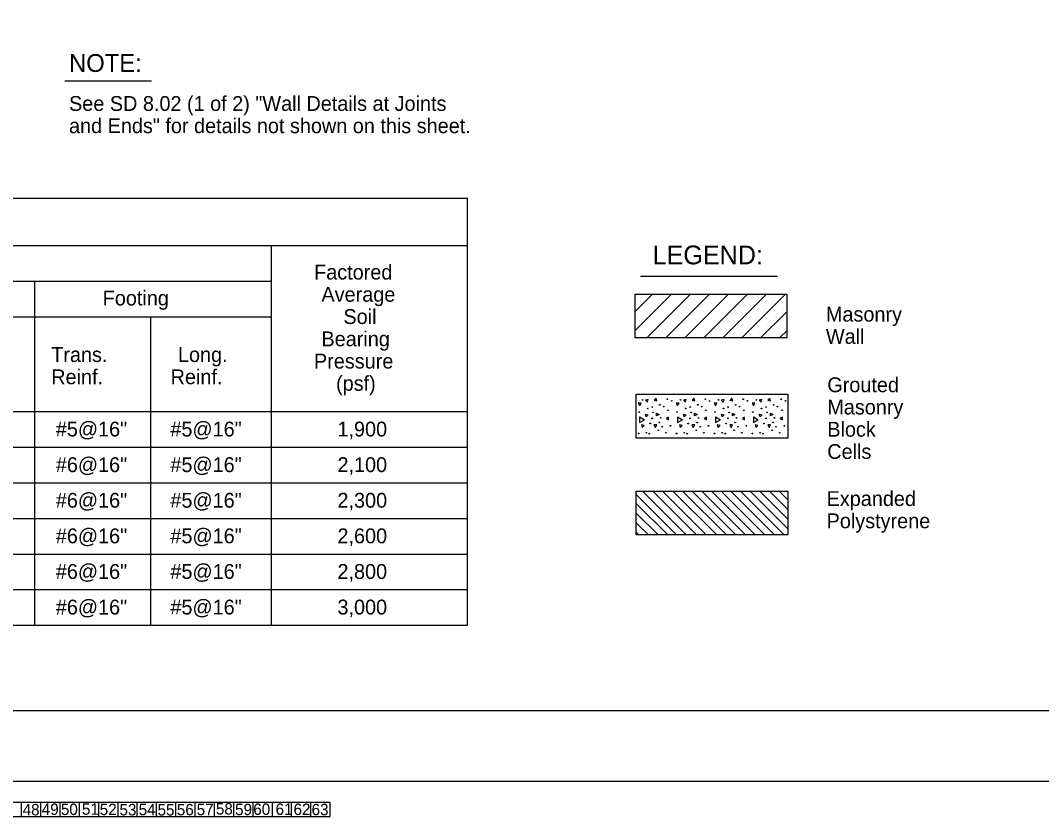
# Model space of a CAD drawing. Extents: x 0 to 2.83, y -0.03 to 1.83.
# Drawn here: x 0.9 to 1.796, y -0.031 to 0.668 of the extents above; entities that cross this region are included whole.
import ezdxf

# ---------------------------------------------------------------- set-up
doc = ezdxf.new("R2010")
doc.units = 0
for name, color, linetype in [('48', 7, 'Continuous'), ('49', 7, 'Continuous'), ('50', 7, 'Continuous'), ('51', 7, 'Continuous'), ('52', 7, 'Continuous'), ('53', 7, 'Continuous'), ('54', 7, 'Continuous'), ('55', 7, 'Continuous'), ('56', 7, 'Continuous'), ('57', 7, 'Continuous'), ('58', 7, 'Continuous'), ('59', 7, 'Continuous'), ('60', 7, 'Continuous'), ('61', 7, 'Continuous'), ('62', 7, 'Continuous'), ('63', 7, 'Continuous')]:
    doc.layers.add(name, color=color, linetype=linetype)

msp = doc.modelspace()

# ---------------------------------------------------------------- linework, layer by layer
at = {"layer": '50'}
for p, q in [((1.45497, 0.42794), (1.43957, 0.41254)), ((1.47163, 0.42794), (1.43957, 0.39587)), ((1.48829, 0.42794), (1.44992, 0.38956)), ((1.5049, 0.42794), (1.46651, 0.38956)), ((1.52157, 0.42794), (1.48318, 0.38956)), ((1.53823, 0.42794), (1.49985, 0.38956)), ((1.5549, 0.42794), (1.51652, 0.38956)), ((1.57157, 0.42794), (1.53319, 0.38956)), ((1.5727, 0.41241), (1.54985, 0.38956)), ((1.5727, 0.39575), (1.56651, 0.38956)), ((1.44051, 0.25203), (1.4761, 0.21644)), ((1.44618, 0.25482), (1.48457, 0.21644)), ((1.45525, 0.25482), (1.49364, 0.21644)), ((1.46372, 0.25482), (1.5021, 0.21644)), ((1.47289, 0.25482), (1.51127, 0.21644)), ((1.48135, 0.25482), (1.51973, 0.21644)), ((1.48982, 0.25482), (1.5282, 0.21644)), ((1.49828, 0.25482), (1.53666, 0.21644)), ((1.50674, 0.25482), (1.54512, 0.21644)), ((1.51521, 0.25482), (1.55359, 0.21644)), ((1.52367, 0.25482), (1.56205, 0.21644)), ((1.53213, 0.25482), (1.57051, 0.21644)), ((1.5406, 0.25482), (1.57365, 0.22177)), ((1.54906, 0.25482), (1.57365, 0.23023)), ((1.55752, 0.25482), (1.57365, 0.23869)), ((1.56599, 0.25482), (1.57365, 0.24716)), ((1.44052, 0.24417), (1.46825, 0.21644)), ((1.44052, 0.2357), (1.45978, 0.21644)), ((1.44052, 0.22724), (1.45132, 0.21644)), ((1.44052, 0.21878), (1.44286, 0.21644))]:
    msp.add_line(p, q, dxfattribs=at)
for centre in [(1.44625, 0.33498), (1.46796, 0.33564), (1.47179, 0.33415), (1.47953, 0.33498), (1.50124, 0.33564), (1.50508, 0.33415), (1.51282, 0.33498), (1.53453, 0.33564), (1.53836, 0.33415), (1.5461, 0.33498), (1.56781, 0.33564), (1.57164, 0.33415), (1.44317, 0.32437), (1.4507, 0.32745), (1.45471, 0.32877), (1.45563, 0.32406), (1.46136, 0.33075), (1.46479, 0.32917), (1.46853, 0.32591), (1.47645, 0.32437), (1.48398, 0.32745), (1.48799, 0.32877), (1.48892, 0.32406), (1.49464, 0.33075), (1.49808, 0.32917), (1.50182, 0.32591), (1.50973, 0.32437), (1.51727, 0.32745), (1.52128, 0.32877), (1.5222, 0.32406), (1.52793, 0.33075), (1.53136, 0.32917), (1.5351, 0.32591), (1.54302, 0.32437), (1.55055, 0.32745), (1.55456, 0.32877), (1.55548, 0.32406), (1.56121, 0.33075), (1.56464, 0.32917), (1.56838, 0.32591), (1.4529, 0.31433), (1.45462, 0.31886), (1.46088, 0.31516), (1.46211, 0.31917), (1.48618, 0.31433), (1.4879, 0.31886), (1.49416, 0.31516), (1.49539, 0.31917), (1.51947, 0.31433), (1.52118, 0.31886), (1.52744, 0.31516), (1.52868, 0.31917), (1.55275, 0.31433), (1.55447, 0.31886), (1.56073, 0.31516), (1.56196, 0.31917), (1.44273, 0.30552), (1.44956, 0.30622), (1.45211, 0.30539), (1.46008, 0.30834), (1.46343, 0.31151), (1.46673, 0.30622), (1.47078, 0.31221), (1.47601, 0.30552), (1.48284, 0.30622), (1.48539, 0.30539), (1.49336, 0.30834), (1.49671, 0.31151), (1.50001, 0.30622), (1.50407, 0.31221), (1.50929, 0.30552), (1.51613, 0.30622), (1.51868, 0.30539), (1.52664, 0.30834), (1.52999, 0.31151), (1.53329, 0.30622), (1.53735, 0.31221), (1.54258, 0.30552), (1.54941, 0.30622), (1.55196, 0.30539), (1.55993, 0.30834), (1.56328, 0.31151), (1.56658, 0.30622), (1.57063, 0.31221)]:
    msp.add_circle(centre, 0.000305, dxfattribs=at)
at = {"layer": '51'}
for p, q in [((1.4436, 0.32009), (1.4436, 0.31513)), ((1.4436, 0.32008), (1.4479, 0.31762)), ((1.4436, 0.31513), (1.4479, 0.3176)), ((1.47688, 0.32009), (1.47688, 0.31513)), ((1.47688, 0.32008), (1.48118, 0.31762)), ((1.47688, 0.31513), (1.48118, 0.3176)), ((1.51017, 0.32009), (1.51017, 0.31513)), ((1.51017, 0.32008), (1.51447, 0.31762)), ((1.51017, 0.31513), (1.51447, 0.3176)), ((1.54345, 0.32009), (1.54345, 0.31513)), ((1.54345, 0.32008), (1.54775, 0.31762)), ((1.54345, 0.31513), (1.54775, 0.3176))]:
    msp.add_line(p, q, dxfattribs=at)
at = {"layer": '52'}
for p, q in [((1.44492, 0.33228), (1.44245, 0.33226)), ((1.44245, 0.33227), (1.44368, 0.33012)), ((1.44368, 0.33012), (1.44493, 0.33227)), ((1.45117, 0.33542), (1.44877, 0.33476)), ((1.44877, 0.33477), (1.45052, 0.33301)), ((1.45052, 0.33301), (1.45117, 0.33541)), ((1.45637, 0.33478), (1.45877, 0.33413)), ((1.4581, 0.33654), (1.45638, 0.33478)), ((1.45877, 0.33413), (1.45812, 0.33653)), ((1.4782, 0.33228), (1.47573, 0.33226)), ((1.47573, 0.33227), (1.47697, 0.33012)), ((1.47697, 0.33012), (1.47822, 0.33227)), ((1.48445, 0.33542), (1.48205, 0.33476)), ((1.48205, 0.33477), (1.4838, 0.33301)), ((1.4838, 0.33301), (1.48445, 0.33541)), ((1.48965, 0.33478), (1.49205, 0.33413)), ((1.49138, 0.33654), (1.48967, 0.33478)), ((1.49205, 0.33413), (1.4914, 0.33653)), ((1.51148, 0.33228), (1.50902, 0.33226)), ((1.50902, 0.33227), (1.51025, 0.33012)), ((1.51025, 0.33012), (1.5115, 0.33227)), ((1.51773, 0.33542), (1.51533, 0.33476)), ((1.51533, 0.33477), (1.51708, 0.33301)), ((1.51708, 0.33301), (1.51773, 0.33541)), ((1.52293, 0.33478), (1.52533, 0.33413)), ((1.52467, 0.33654), (1.52295, 0.33478)), ((1.52533, 0.33413), (1.52468, 0.33653)), ((1.54477, 0.33228), (1.5423, 0.33226)), ((1.5423, 0.33227), (1.54353, 0.33012)), ((1.54353, 0.33012), (1.54478, 0.33227)), ((1.55102, 0.33542), (1.54862, 0.33476)), ((1.54862, 0.33477), (1.55037, 0.33301)), ((1.55037, 0.33301), (1.55102, 0.33541)), ((1.55622, 0.33478), (1.55862, 0.33413)), ((1.55795, 0.33654), (1.55623, 0.33478)), ((1.55862, 0.33413), (1.55797, 0.33653)), ((1.45857, 0.32093), (1.45857, 0.32341)), ((1.45857, 0.3234), (1.46072, 0.32218)), ((1.49185, 0.32093), (1.49185, 0.32341)), ((1.49185, 0.3234), (1.494, 0.32218)), ((1.52513, 0.32093), (1.52513, 0.32341)), ((1.52513, 0.3234), (1.52728, 0.32218)), ((1.55842, 0.32093), (1.55842, 0.32341)), ((1.55842, 0.3234), (1.56057, 0.32218)), ((1.44945, 0.3202), (1.4488, 0.32259)), ((1.44882, 0.32259), (1.4512, 0.32196)), ((1.4512, 0.32195), (1.44945, 0.3202)), ((1.46072, 0.32217), (1.45857, 0.32093)), ((1.46693, 0.31869), (1.46908, 0.31744)), ((1.46907, 0.31993), (1.46695, 0.31868)), ((1.46908, 0.31744), (1.46908, 0.31992)), ((1.48273, 0.3202), (1.48208, 0.32259)), ((1.4821, 0.32259), (1.48448, 0.32196)), ((1.48448, 0.32195), (1.48273, 0.3202)), ((1.494, 0.32217), (1.49185, 0.32093)), ((1.50022, 0.31869), (1.50237, 0.31744)), ((1.50235, 0.31993), (1.50023, 0.31868)), ((1.50237, 0.31744), (1.50237, 0.31992)), ((1.51602, 0.3202), (1.51537, 0.32259)), ((1.51538, 0.32259), (1.51777, 0.32196)), ((1.51777, 0.32195), (1.51602, 0.3202)), ((1.52728, 0.32217), (1.52513, 0.32093)), ((1.5335, 0.31869), (1.53565, 0.31744)), ((1.53563, 0.31993), (1.53352, 0.31868)), ((1.53565, 0.31744), (1.53565, 0.31992)), ((1.5493, 0.3202), (1.54865, 0.32259)), ((1.54867, 0.32259), (1.55105, 0.32196)), ((1.55105, 0.32195), (1.5493, 0.3202)), ((1.56057, 0.32217), (1.55842, 0.32093)), ((1.56678, 0.31869), (1.56893, 0.31744)), ((1.56892, 0.31993), (1.5668, 0.31868)), ((1.56893, 0.31744), (1.56893, 0.31992)), ((1.44523, 0.31311), (1.44588, 0.31071)), ((1.44763, 0.31248), (1.44525, 0.3131)), ((1.44588, 0.31071), (1.44763, 0.31247)), ((1.45865, 0.31309), (1.45617, 0.31307)), ((1.45617, 0.31308), (1.45742, 0.31093)), ((1.45742, 0.31093), (1.45865, 0.31308)), ((1.47852, 0.31311), (1.47917, 0.31071)), ((1.48092, 0.31248), (1.47853, 0.3131)), ((1.47917, 0.31071), (1.48092, 0.31247)), ((1.49193, 0.31309), (1.48945, 0.31307)), ((1.48945, 0.31308), (1.4907, 0.31093)), ((1.4907, 0.31093), (1.49193, 0.31308)), ((1.5118, 0.31311), (1.51245, 0.31071)), ((1.5142, 0.31248), (1.51182, 0.3131)), ((1.51245, 0.31071), (1.5142, 0.31247)), ((1.52522, 0.31309), (1.52273, 0.31307)), ((1.52273, 0.31308), (1.52398, 0.31093)), ((1.52398, 0.31093), (1.52522, 0.31308)), ((1.54508, 0.31311), (1.54573, 0.31071)), ((1.54748, 0.31248), (1.5451, 0.3131)), ((1.54573, 0.31071), (1.54748, 0.31247)), ((1.5585, 0.31309), (1.55602, 0.31307)), ((1.55602, 0.31308), (1.55727, 0.31093)), ((1.55727, 0.31093), (1.5585, 0.31308))]:
    msp.add_line(p, q, dxfattribs=at)
at = {"layer": '55'}
for p, q in [((0.13257, 0.51222), (1.29243, 0.51222)), ((1.29243, 0.13722), (1.29243, 0.51222)), ((0.13257, 0.47055), (1.29243, 0.47055)), ((1.1206, 0.13722), (1.1206, 0.47055)), ((0.62096, 0.4393), (1.1206, 0.4393)), ((0.9128, 0.13722), (0.9128, 0.4393)), ((1.56471, 0.44341), (1.44425, 0.44341)), ((0.62096, 0.40805), (1.1206, 0.40805)), ((1.0146, 0.13722), (1.0146, 0.40805)), ((0.13257, 0.32472), (1.29243, 0.32472)), ((0.13257, 0.29347), (1.29243, 0.29347)), ((0.13257, 0.26222), (1.29243, 0.26222)), ((0.13257, 0.23097), (1.29243, 0.23097)), ((0.13257, 0.19972), (1.29243, 0.19972)), ((0.13257, 0.16847), (1.29243, 0.16847)), ((0.13257, 0.13722), (1.29243, 0.13722))]:
    msp.add_line(p, q, dxfattribs=at)
for points in [[(1.43957, 0.42794), (1.5727, 0.42794), (1.5727, 0.38956), (1.43957, 0.38956)], [(1.44052, 0.33997), (1.57365, 0.33997), (1.57365, 0.30159), (1.44052, 0.30159)], [(1.44052, 0.25482), (1.57365, 0.25482), (1.57365, 0.21644), (1.44052, 0.21644)]]:
    msp.add_lwpolyline(points, close=True, dxfattribs=at)
at = {"layer": '57'}
msp.add_line((0.9391, 0.61521), (1.01507, 0.61521), dxfattribs=at)
at = {"layer": '62'}
for p, q in [((0.10494, -0.01804), (1.17174, -0.01804)), ((0.10496, -0.0181), (1.17175, -0.0181)), ((0.90081, -0.01804), (0.90081, -0.03074)), ((0.90082, -0.0181), (0.90082, -0.0308)), ((0.91774, -0.01804), (0.91774, -0.03074)), ((0.91775, -0.0181), (0.91775, -0.0308)), ((0.93468, -0.01804), (0.93468, -0.03074)), ((0.93469, -0.0181), (0.93469, -0.0308)), ((0.95161, -0.01804), (0.95161, -0.03074)), ((0.95162, -0.0181), (0.95162, -0.0308)), ((0.96854, -0.01804), (0.96854, -0.03074)), ((0.96855, -0.0181), (0.96855, -0.0308)), ((0.98548, -0.01804), (0.98548, -0.03074)), ((0.98549, -0.0181), (0.98549, -0.0308)), ((1.00241, -0.01804), (1.00241, -0.03074)), ((1.00242, -0.0181), (1.00242, -0.0308)), ((1.01934, -0.01804), (1.01934, -0.03074)), ((1.01935, -0.0181), (1.01935, -0.0308)), ((1.03628, -0.01804), (1.03628, -0.03074)), ((1.03629, -0.0181), (1.03629, -0.0308)), ((1.05321, -0.01804), (1.05321, -0.03074)), ((1.05322, -0.0181), (1.05322, -0.0308)), ((1.07014, -0.01804), (1.07014, -0.03074)), ((1.07015, -0.0181), (1.07015, -0.0308)), ((1.08708, -0.01804), (1.08708, -0.03074)), ((1.08709, -0.0181), (1.08709, -0.0308)), ((1.10401, -0.01804), (1.10401, -0.03074)), ((1.10402, -0.0181), (1.10402, -0.0308)), ((1.12094, -0.01804), (1.12094, -0.03074)), ((1.12095, -0.0181), (1.12095, -0.0308)), ((1.13788, -0.01804), (1.13788, -0.03074)), ((1.13789, -0.0181), (1.13789, -0.0308)), ((1.15481, -0.01804), (1.15481, -0.03074)), ((1.15482, -0.0181), (1.15482, -0.0308)), ((1.17174, -0.01804), (1.17174, -0.03074)), ((1.17175, -0.0181), (1.17175, -0.0308)), ((0.10494, -0.03074), (1.17174, -0.03074)), ((0.10496, -0.0308), (1.17175, -0.0308))]:
    msp.add_line(p, q, dxfattribs=at)
at = {"layer": '63'}
msp.add_line((2.83333, 0), (0, 0), dxfattribs=at)
msp.add_lwpolyline([(2.72918, 1.77077), (0.10418, 1.77077), (0.10418, 0.06244), (2.72918, 0.06244)], close=True, dxfattribs=at)

# ---------------------------------------------------------------- texts
at = {"layer": '48'}
for p in [(0.90205, -0.02969), (0.90206, -0.02975)]:
    msp.add_text('48', height=0.01, dxfattribs=at).set_placement(p)
at = {"layer": '49'}
for p in [(0.91882, -0.02929), (0.91883, -0.02935)]:
    msp.add_text('49', height=0.01, dxfattribs=at).set_placement(p)
at = {"layer": '50'}
for p in [(0.93563, -0.02938), (0.93564, -0.02944)]:
    msp.add_text('50', height=0.01, dxfattribs=at).set_placement(p)
at = {"layer": '51'}
for p in [(0.95407, -0.02918), (0.95408, -0.02923)]:
    msp.add_text('51', height=0.01, dxfattribs=at).set_placement(p)
at = {"layer": '52'}
for p in [(0.96972, -0.02946), (0.96973, -0.02952)]:
    msp.add_text('52', height=0.01, dxfattribs=at).set_placement(p)
at = {"layer": '53'}
for p in [(0.98705, -0.0297), (0.98707, -0.02976)]:
    msp.add_text('53', height=0.01, dxfattribs=at).set_placement(p)
at = {"layer": '54'}
for p in [(1.0039, -0.02958), (1.00392, -0.02964)]:
    msp.add_text('54', height=0.01, dxfattribs=at).set_placement(p)
at = {"layer": '55'}
for s, height, p in [('Masonry ', 0.013021, (1.60713, 0.4038)), ('Wall', 0.013021, (1.60713, 0.38427)), ('Grouted ', 0.013021, (1.60833, 0.34181)), ('Masonry ', 0.013021, (1.60833, 0.32228)), ('Block ', 0.013021, (1.60833, 0.30275)), ('Cells', 0.013021, (1.60833, 0.28322)), ('Expanded ', 0.013021, (1.60773, 0.24188)), ('Polystyrene', 0.0130208, (1.60773, 0.22235)), ('55', 0.01, (1.02047, -0.02978)), ('55', 0.01, (1.02048, -0.02984))]:
    msp.add_text(s, height=height, dxfattribs=at).set_placement(p)
at = {"layer": '56'}
for p in [(1.03739, -0.02967), (1.03741, -0.02972)]:
    msp.add_text('56', height=0.01, dxfattribs=at).set_placement(p)
at = {"layer": '57'}
for s, height, p in [('NOTE:', 0.015625, (0.94279, 0.62301)), ('See SD 8.02 (1 of 2) "Wall Details at Joints', 0.0130167, (0.94279, 0.58878)), ('and Ends" for details not shown on this sheet.', 0.0130167, (0.94279, 0.56926)), ('LEGEND:', 0.0165, (1.45498, 0.45407)), ('Factored', 0.013025, (1.15787, 0.44074)), ('Footing', 0.013025, (0.97232, 0.41799)), ('Average', 0.013025, (1.16433, 0.42121)), ('Soil ', 0.013025, (1.18361, 0.40168)), ('Bearing', 0.013025, (1.16433, 0.38214)), ('Trans.', 0.013025, (0.92714, 0.36833)), ('Long.', 0.013025, (1.0384, 0.36833)), ('Pressure', 0.013025, (1.15776, 0.36261)), ('Reinf.', 0.013025, (0.92714, 0.34879)), ('Reinf.', 0.013025, (1.03194, 0.34879)), ('(psf)', 0.013025, (1.17715, 0.34308)), ('#5@16"', 0.013025, (0.93118, 0.30292)), ('#5@16"', 0.013025, (1.03176, 0.30293)), ('1,900', 0.013025, (1.17838, 0.30293)), ('#6@16"', 0.013025, (0.93118, 0.27166)), ('#5@16"', 0.013025, (1.03176, 0.27167)), ('2,100', 0.013025, (1.17838, 0.27167)), ('#6@16"', 0.013025, (0.93118, 0.2404)), ('#5@16"', 0.013025, (1.03176, 0.24041)), ('2,300', 0.013025, (1.17838, 0.24041)), ('#6@16"', 0.013025, (0.93118, 0.20914)), ('#5@16"', 0.013025, (1.03176, 0.20915)), ('2,600', 0.013025, (1.17838, 0.20915)), ('#6@16"', 0.013025, (0.93118, 0.17789)), ('#5@16"', 0.013025, (1.03176, 0.17789)), ('2,800', 0.013025, (1.17838, 0.17789)), ('#6@16"', 0.013025, (0.93118, 0.14663)), ('#5@16"', 0.013025, (1.03176, 0.14664)), ('3,000', 0.013025, (1.17838, 0.14664)), ('57', 0.01, (1.05482, -0.02955)), ('57', 0.01, (1.05483, -0.02961))]:
    msp.add_text(s, height=height, dxfattribs=at).set_placement(p)
at = {"layer": '58'}
for p in [(1.07167, -0.02898), (1.07168, -0.02903)]:
    msp.add_text('58', height=0.01, dxfattribs=at).set_placement(p)
at = {"layer": '59'}
for p in [(1.08852, -0.0295), (1.08853, -0.02955)]:
    msp.add_text('59', height=0.01, dxfattribs=at).set_placement(p)
at = {"layer": '60'}
for p in [(1.10448, -0.02929), (1.10449, -0.02935)]:
    msp.add_text('60', height=0.01, dxfattribs=at).set_placement(p)
at = {"layer": '61'}
for p in [(1.12406, -0.02929), (1.12407, -0.02935)]:
    msp.add_text('61', height=0.01, dxfattribs=at).set_placement(p)
at = {"layer": '62'}
for p in [(1.13984, -0.02938), (1.13986, -0.02943)]:
    msp.add_text('62', height=0.01, dxfattribs=at).set_placement(p)
at = {"layer": '63'}
for p in [(1.15568, -0.02958), (1.15569, -0.02963)]:
    msp.add_text('63', height=0.01, dxfattribs=at).set_placement(p)

doc.saveas('drawing.dxf')
